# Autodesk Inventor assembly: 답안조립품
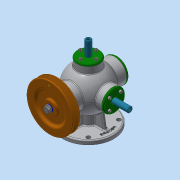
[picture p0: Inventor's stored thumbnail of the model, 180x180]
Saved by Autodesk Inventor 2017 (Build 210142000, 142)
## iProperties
Part Number: 답안조립품
Material: 일반
Document SubType Name: Assembly
Designer: MRC
Author: MRC
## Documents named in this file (17)
- C:\Users\MRC\Desktop\600911V1001\답안조립품.iam
- C:\Users\MRC\Desktop\600911V1001\본체.ipt
- C:\Users\MRC\Desktop\600911V1001\V-벨트풀리.ipt
- C:\Users\MRC\Desktop\600911V1001\너트 M8x1.ipt
- C:\Users\MRC\Desktop\600911V1001\뒤커버.ipt
- C:\Users\MRC\Desktop\600911V1001\베어링 6202.ipt
- C:\Users\MRC\Desktop\600911V1001\본체커버.ipt
- C:\Users\MRC\Desktop\600911V1001\볼트 M4.ipt
- C:\Users\MRC\Desktop\600911V1001\스프링1.ipt
- C:\Users\MRC\Desktop\600911V1001\스프링2.ipt
- C:\Users\MRC\Desktop\600911V1001\슬라이드 커버.ipt
- C:\Users\MRC\Desktop\600911V1001\슬라이드.ipt
- C:\Users\MRC\Desktop\600911V1001\앞커버.ipt
- C:\Users\MRC\Desktop\600911V1001\오일 실.ipt
- C:\Users\MRC\Desktop\600911V1001\와셔 8x17.ipt
- C:\Users\MRC\Desktop\600911V1001\축.ipt
- C:\Users\MRC\Desktop\600911V1001\키 4x4.ipt
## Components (1 placed, 1 different names)
1. V-벨트풀리:1
